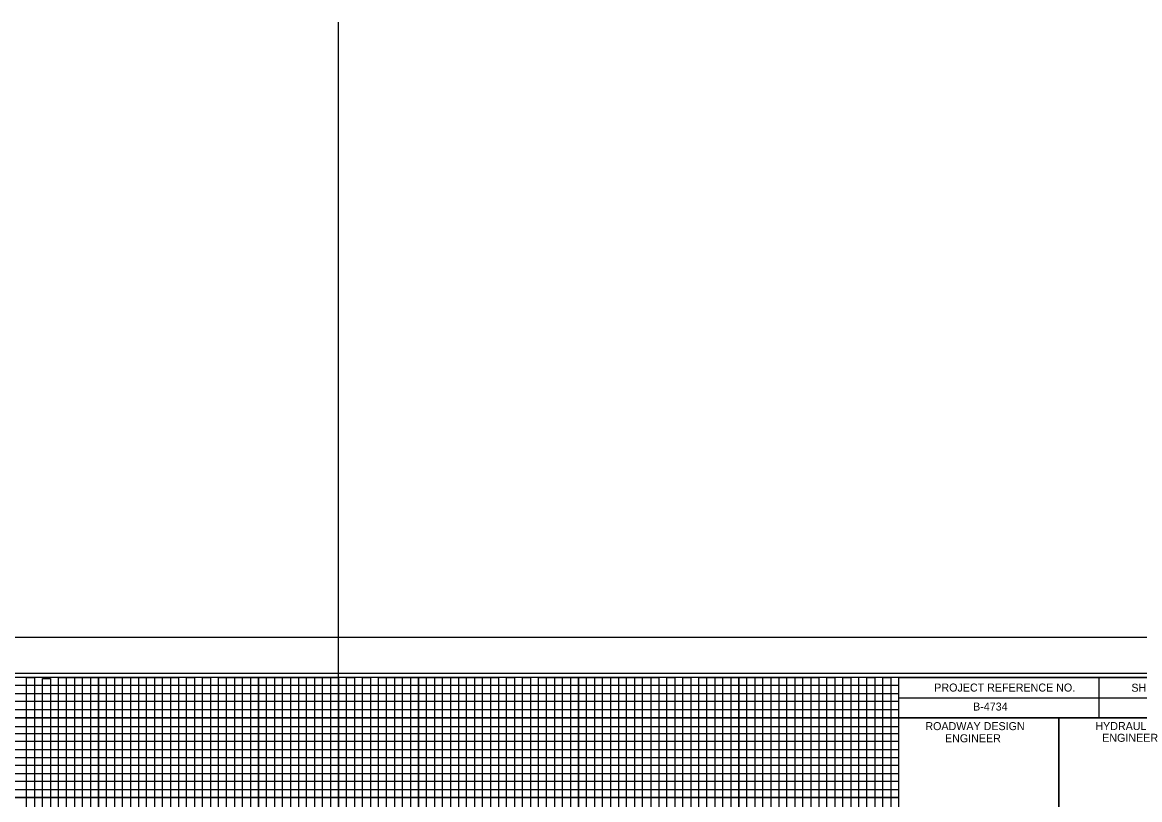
# Model space of a CAD drawing. Extents: x 572269 to 579912, y -56875 to -49627.
# Drawn here: x 574587 to 575285, y -52849 to -52363 of the extents above; entities that cross this region are included whole.
import ezdxf

# ---------------------------------------------------------------- set-up
doc = ezdxf.new("R2010")
doc.units = 0
for name, color, linetype in [('Scratch_Level_5', 7, 'Continuous'), ('Sheet Cutting Line CELL', 7, 'Continuous'), ('Sheet DOT Grid CELL', 7, 'Continuous'), ('Sheet Layout Profile Border', 7, 'Continuous'), ('Sheet Plot Border Inside CELL', 7, 'Continuous'), ('Sheet Plot Border Outside CELL', 7, 'Continuous'), ('Sheet Profile CELL', 7, 'Continuous'), ('Sheet Profile Grid Major CELL', 7, 'Continuous'), ('Sheet Profile Grid Middle CELL', 7, 'Continuous'), ('Sheet Profile Grid Minor CELL', 7, 'Continuous')]:
    doc.layers.add(name, color=color, linetype=linetype)

# ---------------------------------------------------------------- blocks, each defined once
blk = doc.blocks.new('PROFILE SHEET SINGLE')
at = {"layer": 'Sheet Cutting Line CELL'}
blk.add_line((30.34, 21.5), (-3.34, 21.5), dxfattribs=at)
at = {"layer": 'Sheet DOT Grid CELL'}
for p, q in [((16, 21), (16, 0.5)), ((17, 21), (17, 0.5)), ((18, 21), (18, 0.5)), ((19, 21), (19, 0.5)), ((20, 21), (20, 0.5)), ((21, 21), (21, 0.5)), ((22, 21), (22, 0.5)), ((23, 21), (23, 0.5)), ((24, 21), (24, 0.5)), ((25, 21), (25, 0.5)), ((0, 20.5), (25.999, 20.5)), ((0, 19.5), (25.999, 19.5))]:
    blk.add_line(p, q, dxfattribs=at)
at = {"layer": 'Sheet Plot Border Inside CELL'}
blk.add_lwpolyline([(30.25, 21.051), (-3.08, 21.051), (-3.08, -0.051), (30.25, -0.051)], close=True, dxfattribs=at)
at = {"layer": 'Sheet Plot Border Outside CELL'}
blk.add_lwpolyline([(30.34, 21.5), (-3.34, 21.5), (-3.34, -0.5), (30.34, -0.5)], close=True, dxfattribs=at)
at = {"layer": 'Sheet Profile CELL'}
for p, q in [((28.5, 20.999), (28.5, 20.499)), ((25.999, 20.749), (30, 20.749)), ((28, 20.499), (28, 18.25))]:
    blk.add_line(p, q, dxfattribs=at)
for points in [[(30, 21), (0, 21), (0, 0), (30, 0)], [(25.999, 21), (30, 21), (30, 20.499), (25.999, 20.499)], [(25.999, 20.499), (28, 20.499), (28, 18.249), (25.999, 18.249)], [(28, 20.499), (30, 20.499), (30, 18.249), (28, 18.249)]]:
    blk.add_lwpolyline(points, close=True, dxfattribs=at)
at = {"layer": 'Sheet Profile Grid Major CELL'}
for points in [[(16, 0.5), (16, 21), (17, 21), (17, 0.5)], [(18, 0.5), (18, 21), (19, 21), (19, 0.5)], [(20, 0.5), (20, 21), (21, 21), (21, 0.5)], [(22, 0.5), (22, 21), (23, 21), (23, 0.5)], [(24, 0.5), (24, 21), (25, 21), (25, 0.5)], [(26, 0.5), (26, 21), (26.526, 21)], [(25.999, 19.5), (0.002, 19.5), (0.002, 20.499), (25.999, 20.499)]]:
    blk.add_lwpolyline(points, dxfattribs=at)
at = {"layer": 'Sheet Profile Grid Middle CELL'}
for points in [[(15.5, 0.5), (15.5, 21), (16.5, 21), (16.5, 0.5)], [(17.5, 0.5), (17.5, 21), (18.5, 21), (18.5, 0.5)], [(19.5, 0.5), (19.5, 21), (20.5, 21), (20.5, 0.5)], [(21.5, 0.5), (21.5, 21), (22.5, 21), (22.5, 0.5)], [(23.5, 0.5), (23.5, 21), (24.5, 21), (24.5, 0.5)], [(25.5, 0.5), (25.5, 21)], [(0, 20), (25.999, 20)]]:
    blk.add_lwpolyline(points, dxfattribs=at)
at = {"layer": 'Sheet Profile Grid Minor CELL'}
for points in [[(15.1, 0.5), (15.1, 21), (15.2, 21), (15.2, 0.5)], [(15.3, 0.5), (15.3, 20.988), (15.4, 20.988), (15.4, 0.5)], [(15.6, 0.5), (15.6, 21), (15.7, 21), (15.7, 0.5)], [(15.8, 0.5), (15.8, 21), (15.9, 21), (15.9, 0.5)], [(16.1, 0.5), (16.1, 21), (16.2, 21), (16.2, 0.5)], [(16.3, 0.5), (16.3, 21), (16.4, 21), (16.4, 0.5)], [(16.6, 0.5), (16.6, 21), (16.7, 21), (16.7, 0.5)], [(16.8, 0.5), (16.8, 21), (16.9, 21), (16.9, 0.5)], [(17.1, 0.5), (17.1, 21), (17.2, 21), (17.2, 0.5)], [(17.3, 0.5), (17.3, 21), (17.4, 21), (17.4, 0.5)], [(17.6, 0.5), (17.6, 21), (17.7, 21), (17.7, 0.5)], [(17.8, 0.5), (17.8, 21), (17.9, 21), (17.9, 0.5)], [(18.1, 0.5), (18.1, 21), (18.2, 21), (18.2, 0.5)], [(18.3, 0.5), (18.3, 21), (18.4, 21), (18.4, 0.5)], [(18.6, 0.5), (18.6, 21), (18.7, 21), (18.7, 0.5)], [(18.8, 0.5), (18.8, 21), (18.9, 21), (18.9, 0.5)], [(19.1, 0.5), (19.1, 21), (19.2, 21), (19.2, 0.5)], [(19.3, 0.5), (19.3, 21), (19.4, 21), (19.4, 0.5)], [(19.6, 0.5), (19.6, 21), (19.7, 21), (19.7, 0.5)], [(19.8, 0.5), (19.8, 21), (19.9, 21), (19.9, 0.5)], [(20.1, 0.5), (20.1, 21), (20.2, 21), (20.2, 0.5)], [(20.3, 0.5), (20.3, 21), (20.4, 21), (20.4, 0.5)], [(20.6, 0.5), (20.6, 21), (20.7, 21), (20.7, 0.5)], [(20.8, 0.5), (20.8, 21), (20.9, 21), (20.9, 0.5)], [(21.1, 0.5), (21.1, 21), (21.2, 21), (21.2, 0.5)], [(21.3, 0.5), (21.3, 21), (21.4, 21), (21.4, 0.5)], [(21.6, 0.5), (21.6, 21), (21.7, 21), (21.7, 0.5)], [(21.8, 0.5), (21.8, 21), (21.9, 21), (21.9, 0.5)], [(22.1, 0.5), (22.1, 21), (22.2, 21), (22.2, 0.5)], [(22.3, 0.5), (22.3, 21), (22.4, 21), (22.4, 0.5)], [(22.6, 0.5), (22.6, 21), (22.7, 21), (22.7, 0.5)], [(22.8, 0.5), (22.8, 21), (22.9, 21), (22.9, 0.5)], [(23.1, 0.5), (23.1, 21), (23.2, 21), (23.2, 0.5)], [(23.3, 0.5), (23.3, 21), (23.4, 21), (23.4, 0.5)], [(23.6, 0.5), (23.6, 21), (23.7, 21), (23.7, 0.5)], [(23.8, 0.5), (23.8, 21), (23.9, 21), (23.9, 0.5)], [(24.1, 0.5), (24.1, 21), (24.2, 21), (24.2, 0.5)], [(24.3, 0.5), (24.3, 21), (24.4, 21), (24.4, 0.5)], [(24.6, 0.5), (24.6, 21), (24.7, 21), (24.7, 0.5)], [(24.8, 0.5), (24.8, 21), (24.9, 21), (24.9, 0.5)], [(25.1, 0.5), (25.1, 21), (25.2, 21), (25.2, 0.5)], [(25.3, 0.5), (25.3, 21), (25.4, 21), (25.4, 0.5)], [(25.6, 0.5), (25.6, 21), (25.7, 21), (25.7, 0.5)], [(25.8, 0.5), (25.8, 21), (25.9, 21), (25.9, 0.5)], [(25.999, 20.9), (1, 20.9), (1, 20.8), (25.999, 20.8)], [(25.999, 20.7), (1, 20.7), (1, 20.6), (25.999, 20.6)], [(25.999, 20.385), (1.02, 20.385), (1.02, 20.3), (25.999, 20.3)], [(25.999, 20.2), (1, 20.2), (1, 20.1), (25.999, 20.1)], [(25.999, 19.9), (1, 19.9), (1, 19.8), (25.999, 19.8)], [(25.999, 19.7), (1, 19.7), (1, 19.6), (25.999, 19.6)]]:
    blk.add_lwpolyline(points, dxfattribs=at)
at = {"layer": 'Sheet Profile CELL'}
for s, p in [('PROJECT REFERENCE NO.', (26.443, 20.826)), ('SHEET NO.', (28.906, 20.824)), ('ROADWAY DESIGN', (26.332, 20.344)), ('HYDRAULICS', (28.456, 20.345)), ('ENGINEER', (26.577, 20.192)), ('ENGINEER', (28.541, 20.198))]:
    blk.add_text(s, height=0.1, dxfattribs=at).set_placement(p)

msp = doc.modelspace()

# ---------------------------------------------------------------- linework, layer by layer
at = {"layer": 'Scratch_Level_5'}
msp.add_line((574784.69, -53797.71), (574784.69, -52363.21), dxfattribs=at)
at = {"layer": 'Sheet Layout Profile Border'}
msp.add_lwpolyline([(573884.69, -52772.71), (573884.69, -53797.71), (575284.69, -53797.71), (575284.69, -52910.26), (575134.64, -52910.26), (575134.64, -52772.71)], close=True, dxfattribs=at)

# ---------------------------------------------------------------- block references
at = {"layer": 'Sheet Cutting Line CELL', "xscale": 50, "yscale": 50}
msp.add_blockref('PROFILE SHEET SINGLE', (573834.69, -53822.71), dxfattribs=at)

# ---------------------------------------------------------------- texts
at = {"layer": 'Sheet Profile CELL'}
msp.add_text('B-4734', height=5, dxfattribs=at).set_placement((575181.1, -52793.29))

doc.saveas('drawing.dxf')
